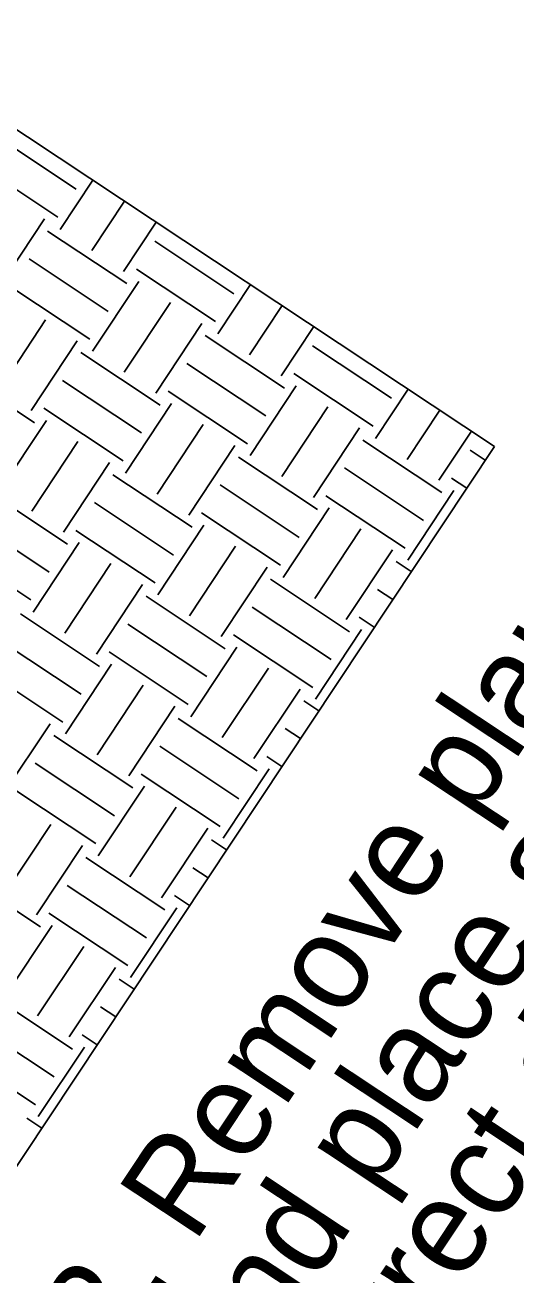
# Model space of a CAD drawing. Extents: x 561231 to 564935, y 589159 to 602519.
# Drawn here: x 564273.4 to 564294.2, y 589735.2 to 589788.1 of the extents above; entities that cross this region are included whole.
import ezdxf

# ---------------------------------------------------------------- set-up
doc = ezdxf.new("R2010")
doc.units = 0
doc.layers.add('Old_Level_1', color=7, linetype='Continuous')

msp = doc.modelspace()

# ---------------------------------------------------------------- linework, layer by layer
at = {"layer": 'Old_Level_1'}
for p, q in [((564266.371, 589788.081), (564293.258, 589770.243)), ((564272.226, 589783.347), (564275.571, 589781.127)), ((564271.445, 589782.168), (564274.79, 589779.949)), ((564274.891, 589779.426), (564276.274, 589781.512)), ((564276.229, 589778.539), (564277.612, 589780.624)), ((564272.268, 589776.925), (564274.222, 589779.87)), ((564277.567, 589777.651), (564278.95, 589779.736)), ((564274.361, 589779.354), (564277.706, 589777.134)), ((564278.893, 589778.924), (564282.238, 589776.704)), ((564273.579, 589778.175), (564276.925, 589775.956)), ((564278.112, 589777.745), (564281.457, 589775.526)), ((564276.259, 589774.277), (564278.213, 589777.222)), ((564281.558, 589775.003), (564282.941, 589777.088)), ((564272.798, 589776.997), (564276.143, 589774.778)), ((564277.597, 589773.389), (564279.551, 589776.335)), ((564282.896, 589774.115), (564284.279, 589776.2)), ((564272.322, 589772.647), (564274.276, 589775.593)), ((564278.935, 589772.501), (564280.889, 589775.447)), ((564284.234, 589773.227), (564285.617, 589775.313)), ((564273.66, 589771.759), (564275.613, 589774.705)), ((564281.028, 589774.93), (564284.373, 589772.711)), ((564285.56, 589774.5), (564288.905, 589772.281)), ((564275.767, 589774.211), (564279.113, 589771.991)), ((564270.454, 589773.462), (564273.8, 589771.243)), ((564280.246, 589773.752), (564283.592, 589771.533)), ((564274.986, 589773.032), (564278.331, 589770.813)), ((564284.778, 589773.322), (564288.124, 589771.103)), ((564279.465, 589772.574), (564282.811, 589770.355)), ((564282.927, 589769.853), (564284.879, 589772.799)), ((564288.225, 589770.58), (564289.608, 589772.665)), ((564274.205, 589771.854), (564277.55, 589769.635)), ((564277.651, 589769.112), (564279.605, 589772.057)), ((564284.265, 589768.965), (564286.218, 589771.912)), ((564272.352, 589768.385), (564274.306, 589771.332)), ((564289.563, 589769.692), (564290.946, 589771.777)), ((564278.989, 589768.224), (564280.943, 589771.169)), ((564285.603, 589768.078), (564287.556, 589771.024)), ((564290.901, 589768.804), (564292.284, 589770.889)), ((564270.035, 589735.227), (564293.258, 589770.243)), ((564273.69, 589767.498), (564275.644, 589770.444)), ((564280.327, 589767.336), (564282.281, 589770.282)), ((564287.695, 589770.507), (564291.041, 589768.288)), ((564282.435, 589769.787), (564285.78, 589767.568)), ((564292.227, 589770.077), (564292.866, 589769.653)), ((564275.029, 589766.61), (564276.982, 589769.556)), ((564286.914, 589769.329), (564290.259, 589767.11)), ((564277.121, 589769.04), (564280.467, 589766.82)), ((564291.446, 589768.899), (564292.085, 589768.475)), ((564271.861, 589768.319), (564275.206, 589766.1)), ((564281.653, 589768.609), (564284.998, 589766.39)), ((564286.133, 589768.151), (564289.478, 589765.931)), ((564289.593, 589765.43), (564291.547, 589768.376)), ((564276.34, 589767.861), (564279.685, 589765.642)), ((564284.318, 589764.689), (564286.272, 589767.634)), ((564271.079, 589767.141), (564274.424, 589764.922)), ((564280.872, 589767.431), (564284.217, 589765.211)), ((564275.559, 589766.683), (564278.904, 589764.463)), ((564279.019, 589763.962), (564280.973, 589766.908)), ((564285.656, 589763.801), (564287.61, 589766.746)), ((564273.744, 589763.221), (564275.697, 589766.166)), ((564280.357, 589763.074), (564282.311, 589766.02)), ((564270.298, 589765.963), (564273.643, 589763.743)), ((564286.994, 589762.913), (564288.948, 589765.859)), ((564275.082, 589762.333), (564277.035, 589765.278)), ((564281.696, 589762.187), (564283.649, 589765.132)), ((564289.102, 589765.364), (564289.74, 589764.94)), ((564276.42, 589761.445), (564278.374, 589764.391)), ((564283.788, 589764.616), (564287.134, 589762.397)), ((564278.528, 589763.896), (564281.873, 589761.677)), ((564288.32, 589764.186), (564288.959, 589763.762)), ((564283.007, 589763.438), (564286.352, 589761.218)), ((564273.214, 589763.148), (564276.559, 589760.929)), ((564287.539, 589763.008), (564288.178, 589762.584)), ((564277.746, 589762.718), (564281.091, 589760.498)), ((564285.686, 589759.539), (564287.64, 589762.485)), ((564272.433, 589761.97), (564275.778, 589759.75)), ((564280.411, 589758.797), (564282.364, 589761.743)), ((564282.225, 589762.26), (564285.571, 589760.04)), ((564276.965, 589761.54), (564280.31, 589759.32)), ((564271.651, 589760.792), (564274.997, 589758.572)), ((564275.112, 589758.071), (564277.066, 589761.017)), ((564281.749, 589757.91), (564283.703, 589760.855)), ((564276.451, 589757.183), (564278.404, 589760.129)), ((564283.087, 589757.022), (564285.041, 589759.967)), ((564277.789, 589756.296), (564279.742, 589759.241)), ((564285.195, 589759.473), (564285.834, 589759.049)), ((564279.881, 589758.725), (564283.226, 589756.505)), ((564272.513, 589755.554), (564274.467, 589758.5)), ((564284.413, 589758.295), (564285.052, 589757.871)), ((564274.62, 589758.005), (564277.966, 589755.785)), ((564279.1, 589757.547), (564282.445, 589755.327)), ((564283.632, 589757.116), (564284.271, 589756.692)), ((564273.839, 589756.827), (564277.184, 589754.607)), ((564281.78, 589753.648), (564283.733, 589756.593)), ((564278.318, 589756.368), (564281.664, 589754.149)), ((564273.058, 589755.648), (564276.403, 589753.429)), ((564276.504, 589752.906), (564278.458, 589755.852)), ((564277.842, 589752.018), (564279.796, 589754.964)), ((564272.544, 589751.292), (564274.497, 589754.238)), ((564279.18, 589751.131), (564281.134, 589754.076)), ((564273.882, 589750.404), (564275.835, 589753.35)), ((564281.287, 589753.582), (564281.926, 589753.158)), ((564275.974, 589752.834), (564279.32, 589750.614)), ((564280.506, 589752.403), (564281.145, 589751.979)), ((564270.713, 589752.114), (564274.059, 589749.894)), ((564275.193, 589751.655), (564278.538, 589749.436)), ((564279.725, 589751.225), (564280.363, 589750.801)), ((564277.872, 589747.757), (564279.826, 589750.702)), ((564274.412, 589750.477), (564277.757, 589748.258)), ((564272.597, 589747.015), (564274.551, 589749.96)), ((564273.936, 589746.127), (564275.889, 589749.073)), ((564275.274, 589745.239), (564277.227, 589748.185)), ((564277.381, 589747.69), (564278.019, 589747.266)), ((564272.067, 589746.942), (564275.413, 589744.723)), ((564276.599, 589746.512), (564277.238, 589746.088)), ((564271.286, 589745.764), (564274.631, 589743.544)), ((564275.818, 589745.334), (564276.457, 589744.91)), ((564270.504, 589744.586), (564273.85, 589742.367)), ((564273.966, 589741.865), (564275.919, 589744.811)), ((564273.474, 589741.799), (564274.113, 589741.376))]:
    msp.add_line(p, q, dxfattribs=at)

# ---------------------------------------------------------------- texts
for s, p in [('2. Remove planting bar ', (564277.251, 589731.464)), (' and place seedling at ', (564281.552, 589728.612)), (' correct depth.', (564285.854, 589725.759))]:
    msp.add_text(s, height=4.01452, rotation=56.4482, dxfattribs=at).set_placement(p)

doc.saveas('drawing.dxf')
